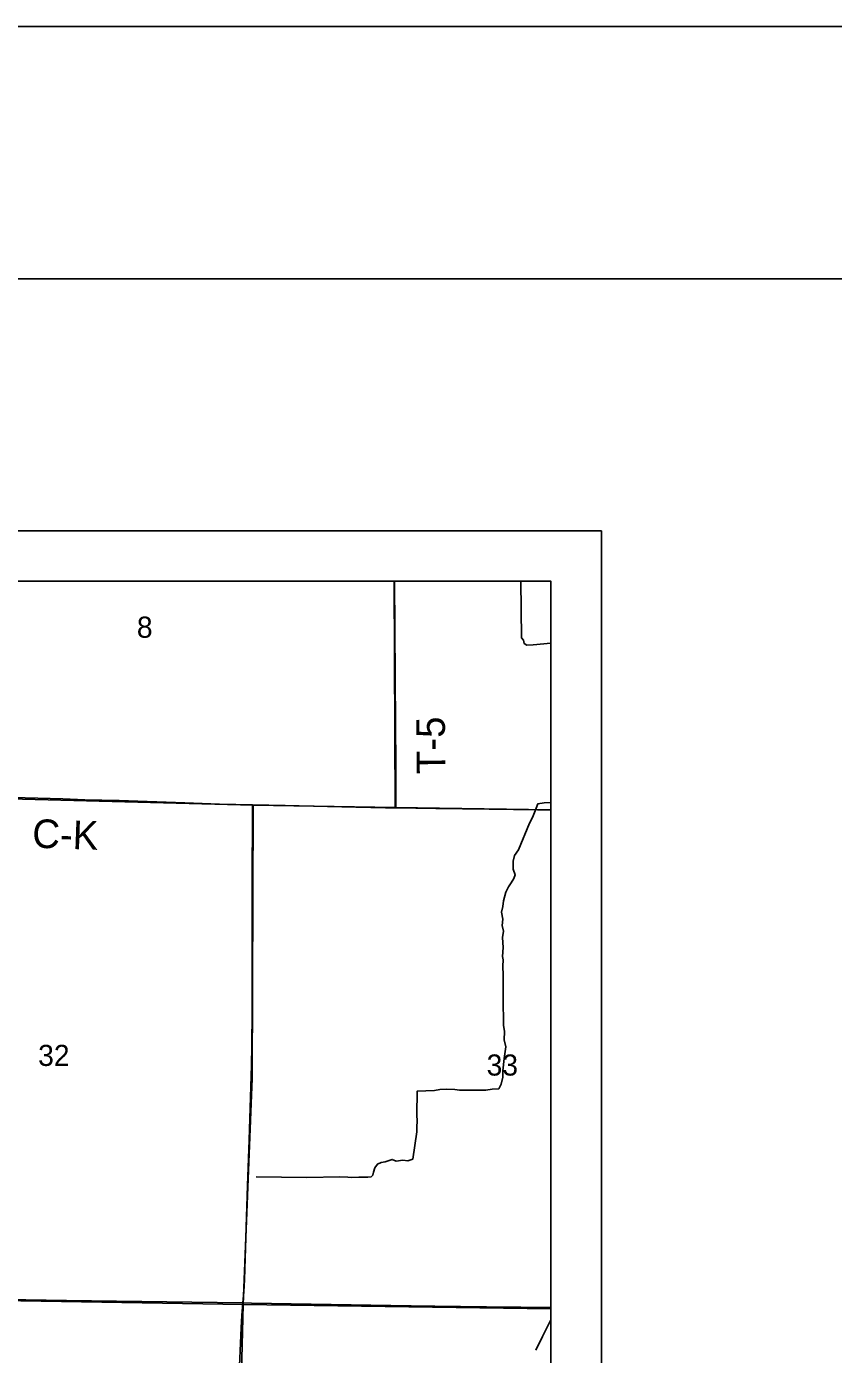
# Model space of a CAD drawing. Extents: x 0 to 42, y 0 to 22.
# Drawn here: x 7.86 to 9.46, y 19.367 to 22 of the extents above; entities that cross this region are included whole.
import ezdxf

# ---------------------------------------------------------------- set-up
doc = ezdxf.new("R2010")
doc.units = 0
for name, color, linetype in [('Default', 7, 'Continuous'), ('GM_X_County_Road', 7, 'Continuous'), ('GM_X_County_Road_Text', 7, 'Continuous'), ('GM_X_Interchange_Ramps', 7, 'Continuous'), ('GM_X_Minor_River', 7, 'Continuous'), ('GM_X_Section', 7, 'Continuous'), ('GM_X_Section_Text', 7, 'Continuous'), ('GM_X_Township_Road', 7, 'Continuous'), ('GM_X_Township_Road_Text', 7, 'Continuous'), ('SH_Border', 7, 'Continuous'), ('SH_Cut_Line', 7, 'Continuous'), ('SH_Data', 7, 'Continuous')]:
    doc.layers.add(name, color=color, linetype=linetype)

msp = doc.modelspace()

# ---------------------------------------------------------------- linework, layer by layer
at = {"layer": 'Default'}
for points in [[(8.5893, 20.9), (7.6, 20.9), (7.5963, 20.4744), (8.3092, 20.4559), (8.5911, 20.4514)], [(8.9, 20.4464), (8.9, 20.9), (8.5893, 20.9), (8.5911, 20.4514)], [(8.9, 19.4571), (8.9, 20.4464), (8.5911, 20.4514), (8.3092, 20.4559), (8.3071, 19.914), (8.2893, 19.4656)], [(8.9, 18.4589), (8.9, 19.4571), (8.2893, 19.4656), (8.2652, 18.4704)]]:
    msp.add_lwpolyline(points, close=True, dxfattribs=at)
at = {"layer": 'GM_X_County_Road'}
for points in [[(7.8038, 20.472), (7.8571, 20.4705), (7.9317, 20.4681), (7.9752, 20.4667), (8.0436, 20.4648), (8.1741, 20.4605), (8.2425, 20.4581), (8.3077, 20.4565)], [(8.3077, 20.4565), (8.373, 20.4549), (8.429, 20.4539), (8.4569, 20.4531), (8.5129, 20.4519), (8.572, 20.4505), (8.5924, 20.4503)], [(8.5924, 20.4503), (8.6715, 20.4492), (8.7772, 20.4479), (8.8736, 20.4464), (8.9, 20.4461)], [(7.787, 19.4762), (7.8178, 19.4757), (7.9391, 19.4738), (8.1877, 19.4699), (8.2889, 19.4687)], [(8.2889, 19.4687), (8.3059, 19.4685), (8.5825, 19.4638), (8.6229, 19.4631), (8.6696, 19.4625), (8.7721, 19.4609), (8.8405, 19.4601), (8.9, 19.4599)]]:
    msp.add_lwpolyline(points, dxfattribs=at)
at = {"layer": 'GM_X_Interchange_Ramps'}
msp.add_lwpolyline([(8.9, 18.4589), (8.9, 20.9), (6.4601, 20.9), (6.459, 20.4888), (6.4167, 20.4908), (6.3001, 20.4958), (6.299, 20.4627), (6.298, 20.4191), (6.2959, 20.2948), (6.2915, 20.006), (6.2868, 19.7794), (6.2827, 19.5494), (6.2823, 19.5012), (6.2823, 19.4965), (6.2766, 19.154)], dxfattribs=at)
at = {"layer": 'GM_X_Minor_River'}
for points in [[(8.8405, 20.9), (8.8414, 20.7874), (8.8455, 20.7828), (8.8469, 20.7763), (8.8521, 20.7732), (8.865, 20.7741), (8.9, 20.777)], [(8.9, 20.4611), (8.8863, 20.4607), (8.8742, 20.4587), (8.8689, 20.4444), (8.8634, 20.4316), (8.8575, 20.4203), (8.8356, 20.3676), (8.8278, 20.356), (8.8252, 20.3446), (8.8253, 20.3287), (8.8289, 20.318), (8.8265, 20.3104), (8.8214, 20.3018), (8.8159, 20.294), (8.8104, 20.2831), (8.8059, 20.2661), (8.8045, 20.2547), (8.802, 20.2437), (8.8044, 20.23), (8.8033, 20.2171), (8.8061, 20.2057), (8.804, 20.1932), (8.8051, 20.1734), (8.804, 20.156), (8.805, 20.1491), (8.8044, 20.1366), (8.8055, 20.1184), (8.8053, 20.1062), (8.8055, 20.0967), (8.8055, 20.0618), (8.8056, 20.0303), (8.8062, 20.0196), (8.8078, 20.0067), (8.8075, 19.9904), (8.8102, 19.9766), (8.8071, 19.9535), (8.8043, 19.9289), (8.8045, 19.9164), (8.8011, 19.9028), (8.7964, 19.8934), (8.7835, 19.8925), (8.771, 19.8905), (8.7187, 19.8904), (8.7092, 19.8917), (8.6937, 19.8928), (8.6793, 19.8919), (8.6687, 19.8899), (8.6349, 19.889), (8.634, 19.842), (8.6345, 19.8294), (8.6343, 19.818), (8.6337, 19.8082), (8.6258, 19.754), (8.6158, 19.7504), (8.6064, 19.7518), (8.5931, 19.7498), (8.5848, 19.7533), (8.5711, 19.7483), (8.5635, 19.7473), (8.5558, 19.7437), (8.5508, 19.7369), (8.5483, 19.7283), (8.5467, 19.7218), (8.5432, 19.7189), (8.5371, 19.7182), (8.5296, 19.718), (8.519, 19.7182), (8.5053, 19.7174), (8.4974, 19.7179), (8.4811, 19.719), (8.4159, 19.7176), (8.3155, 19.7189)]]:
    msp.add_lwpolyline(points, dxfattribs=at)
at = {"layer": 'GM_X_Section'}
for points in [[(7.3083, 20.4793), (7.5963, 20.4744), (8.3092, 20.4559), (8.3071, 19.914), (8.2893, 19.4656), (7.2872, 19.4822)], [(7.2774, 19.4824), (7.2872, 19.4822), (8.2893, 19.4656), (8.2652, 18.4704), (7.2453, 18.4817)]]:
    msp.add_lwpolyline(points, close=True, dxfattribs=at)
at = {"layer": 'GM_X_Township_Road'}
for points in [[(8.5924, 20.4503), (8.5924, 20.4567), (8.5925, 20.4722), (8.5923, 20.5374), (8.5916, 20.6151), (8.5898, 20.9)], [(8.2889, 19.4687), (8.2908, 19.4904), (8.2922, 19.5152), (8.2984, 19.7015), (8.3011, 19.7915), (8.306, 19.9405), (8.3068, 19.9778), (8.3071, 20.0461), (8.3073, 20.2015), (8.3075, 20.2978), (8.3077, 20.4469), (8.3077, 20.4565)], [(8.3077, 20.4565), (8.373, 20.4549), (8.429, 20.4539), (8.4569, 20.4531), (8.5129, 20.4519), (8.572, 20.4505), (8.5924, 20.4503)], [(7.787, 19.4762), (7.8178, 19.4757), (7.9391, 19.4738), (8.1877, 19.4699), (8.2889, 19.4687)], [(8.2675, 18.8442), (8.2678, 18.9193), (8.2683, 18.966), (8.2699, 19.0188), (8.2729, 19.0995), (8.2757, 19.1741), (8.2763, 19.1891), (8.281, 19.3136), (8.2853, 19.4191), (8.2867, 19.444), (8.2889, 19.4687)], [(8.2889, 19.4687), (8.3059, 19.4685), (8.5825, 19.4638), (8.6229, 19.4631), (8.6696, 19.4625), (8.7721, 19.4609), (8.8405, 19.4601), (8.9, 19.4599)], [(8.87, 19.3752), (8.883, 19.402), (8.9, 19.4352)]]:
    msp.add_lwpolyline(points, dxfattribs=at)
at = {"layer": 'SH_Border'}
msp.add_lwpolyline([(1.5, 21.5), (33.5, 21.5), (33.5, 0.5), (1.5, 0.5)], close=True, dxfattribs=at)
at = {"layer": 'SH_Cut_Line'}
msp.add_lwpolyline([(0, 0), (34, 0), (34, 22), (0, 22)], close=True, dxfattribs=at)
at = {"layer": 'SH_Data'}
for p, q in [((2, 21), (9, 21)), ((9, 21), (9, 14)), ((2.1, 20.9), (8.9, 20.9)), ((8.9, 20.9), (8.9, 14.1))]:
    msp.add_line(p, q, dxfattribs=at)

# ---------------------------------------------------------------- texts
at = {"layer": 'GM_X_County_Road_Text'}
msp.add_text('C-K', height=0.05682, rotation=358.0099, dxfattribs=at).set_placement((7.8704, 20.3717))
at = {"layer": 'GM_X_Section_Text'}
for s, height, p in [('8', 0.0419, (8.0787, 20.7879)), ('32', 0.04186, (7.8829, 19.9387)), ('33', 0.04186, (8.7724, 19.9196))]:
    msp.add_text(s, height=height, rotation=0, dxfattribs=at).set_placement(p)
at = {"layer": 'GM_X_Township_Road_Text'}
msp.add_text('T-5', height=0.05682, rotation=90.4772, dxfattribs=at).set_placement((8.6905, 20.5178))

doc.saveas('drawing.dxf')
